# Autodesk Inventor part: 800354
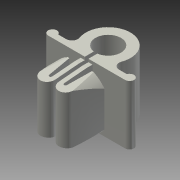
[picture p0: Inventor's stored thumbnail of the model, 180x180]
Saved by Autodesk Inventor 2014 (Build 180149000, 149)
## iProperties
Created: 2007-11
Part Number: 800354
Document SubType Name: Modeling
Designer: RH
Density: 1.06 g/cm^3
Mass: 0.664366 g
Surface Area: 10.9214 cm^2
Volume: 0.626761 cm^3
Material: ABS Plastic
Description: WIRE CLIP
Appearance: Smooth - Ivory
Component Category: Fasteners
Author: RH
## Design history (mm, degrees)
sketch "Sketch1"
  geometry: L1 (-5.793, -2.643)-(-4.457, -2.643); L2 (5.793, -2.643)-(4.457, -2.643); L3 (-0.3, -2.139)-(-0.3, -8.643); L4 (0.3, -2.139)-(0.3, -3.643); L5 (-2.751, -8.988)-(-4, -4.643); L6 (-4, -4.643)-(-1.9, -4.643); L7 (-1.9, -4.643)-(-1.499, -8.469); L8 (-1, -3.643)-(-1, -8.443); L9 (-12.873, -3.643)-(-1, -3.643); L10 (1, -3.643)-(16.288, -3.643); L11 (0, 6.511)-(0, -12.814) reference; L12 (4, -4.643)-(1.9, -4.643); L13 (1, -3.643)-(1, -8.443); L14 (1.9, -4.643)-(1.499, -8.469); L15 (2.751, -8.988)-(4, -4.643); L16 (0.3, -2.139)-(0.3, -8.643); A1 r 2.16 centre (0, 0) between (-0.3, -2.139) and (0.3, -2.139); A2 r 0.75 centre (-6.5, -2.893) between (-5.793, -2.643) and (-6.5, -3.643); A3 r 0.75 centre (6.5, -2.893) between (6.5, -3.643) and (5.793, -2.643); A4 r 3.75 centre (0, 0) between (3.519, -1.297) and (-3.519, -1.297); A5 r 1 centre (-4.457, -1.643) between (-4.457, -2.643) and (-3.519, -1.297); A6 r 1 centre (4.457, -1.643) between (3.519, -1.297) and (4.457, -2.643); A7 r 1.25 centre (-1.55, -8.643) between (-2.751, -8.988) and (-0.3, -8.643); A8 r 0.25 centre (-1.25, -8.443) between (-1.499, -8.469) and (-1, -8.443); A9 r 0.25 centre (1.25, -8.443) between (1, -8.443) and (1.499, -8.469); A10 r 1.25 centre (1.55, -8.643) between (0.3, -8.643) and (2.751, -8.988); 1 further point
  constraints: 30 end point, 20 point on circle, 12 tangent, 10 centre point, 9 symmetric about line, 3 parallel, 3 perpendicular, 2 coincident, 2 horizontal, 2 point on line, 1 collinear, 1 equal radius, 2 other
  dimensions: "d0" = 4.32 diameter of A1; "d5" = 1.5 diameter of A2; "d6" = 1.5 diameter of A3 (= d5); "d7" = 6.5 horizontal distance of point (0, 0) A2.centre; "d8" = 6.5 horizontal distance of point (0, 0) A3.centre (= d7); "d9" = 3.75 radius of A4; "d10" = 1 radius of A5; "d11" = 0.6 distance between parallel lines of L3 L4; "d12" = 0.3 distance from line of point (0, 0) L3 (= 0.5 x d11); "d13" = 0.5 diameter of A8; "d14" = 2.5 diameter of A7; "d15" = 4 horizontal distance of point (0, 0) L5.end; "d17" = 2.1 distance of L5.end L6.end; "d18" = 0.2 vertical distance of A7.centre A8.centre; "d19" = 0.7 distance between parallel lines of L8 L3; "d21" = 3.643 distance from line of point (0, 0) L9; "d22" = 1 distance between parallel lines of L9 L1; "d23" = 1 distance between parallel lines of L10 L2; "d24" = 5 distance from line of L9 A7.centre; "d25" = 1 distance between parallel lines of L9 L6
extrude "Extrusion1" new body sketch "Sketch1" stored distance "d26" = 10; taper "d27" = 0 deg
sketch "Sketch2"
  geometry: C1 r 10 at (-1, -5); C2 r 5 at (-1, -5); 1 further point
  constraints: 2 centre point, 2 coincident
  dimensions: "d28" = 10 diameter of C2; "d29" = 5 radial gap between concentric circles of C2 C1
extrude "Extrusion2" cut sketch "Sketch2" stored distance "d30" = 10; taper "d31" = 0 deg
sketch "Sketch3"
  geometry: L1 (-3.643, 5)-(-3.643, 4.991) reference; L2 (-3.643, -5)-(-3.643, 5) reference; L3 (-3.643, -4.991)-(-3.643, -5) reference; L4 (-3.643, -4.899)-(-3.643, -4.991) reference; L5 (-3.643, -4.899)-(-3.643, 4.899) reference; L6 (-3.643, 4.991)-(-3.643, 4.899) reference; L7 (-3.643, 5)-(-3.643, 4.5); L8 (-11.643, 3.888)-(-11.643, 6); L9 (-11.643, 6)-(-3.643, 6); L10 (-3.643, 6)-(-3.643, 5); L11 (-3.643, 4.5)-(-4.643, 4.5); L12 (-4.643, 4.5)-(-11.643, 3.888); L13 (-13.972, 0)-(2.329, 0) reference; L14 (-3.643, -4.991)-(-3.643, -4.899); L15 (-3.643, -5)-(-3.643, -4.991); L16 (-3.643, -5)-(-3.643, -4.5); L17 (-3.643, -6)-(-3.643, -5); L18 (-4.643, -4.5)-(-11.643, -3.888); L19 (-11.643, -3.888)-(-11.643, -6); L20 (-11.643, -6)-(-3.643, -6); L21 (-3.643, -4.5)-(-4.643, -4.5); 1 further point
  constraints: 28 end point, 7 symmetric about line, 2 perpendicular, 1 collinear, 1 parallel, 1 point on line
  dimensions: "d32" = 1 distance of L7.end L11.end; "d33" = 5 deg angle of L11 L12; "d34" = 0.5 distance from line of L11 L1.start; "d35" = 1 distance of L9.end L2.end; "d36" = 8 distance of L8.end L9.end
extrude "Extrusion3" cut sketch "Sketch3" stored distance "d37" = 10; taper "d38" = 0 deg
body "Solid1"
node "Projected Loop1"
other parameters: "d1" = 7.5, "d2" = 3.643, "d3" = 1, "d4" = 1 (= d3), "d16" = 1, "d20" = 5
